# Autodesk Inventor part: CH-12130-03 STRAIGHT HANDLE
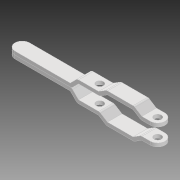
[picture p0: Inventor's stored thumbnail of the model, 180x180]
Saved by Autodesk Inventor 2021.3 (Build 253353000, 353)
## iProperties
Created: 2020-03
Part Number: CH-12130-03 STRAIGHT HANDLE
Material: Ogólny
Document SubType Name: Modeling
Designer: Przemyslaw Krecisz
Density: 1 g/cm^3
Appearance: Domyślna
Author: Przemyslaw Krecisz
Revision Number: ÈÎºÎ
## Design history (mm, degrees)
feature "ÇÐ³ý-À­Éì1"
feature "¾µÏò1"
node "Bryła1"
node "Bryła2"
